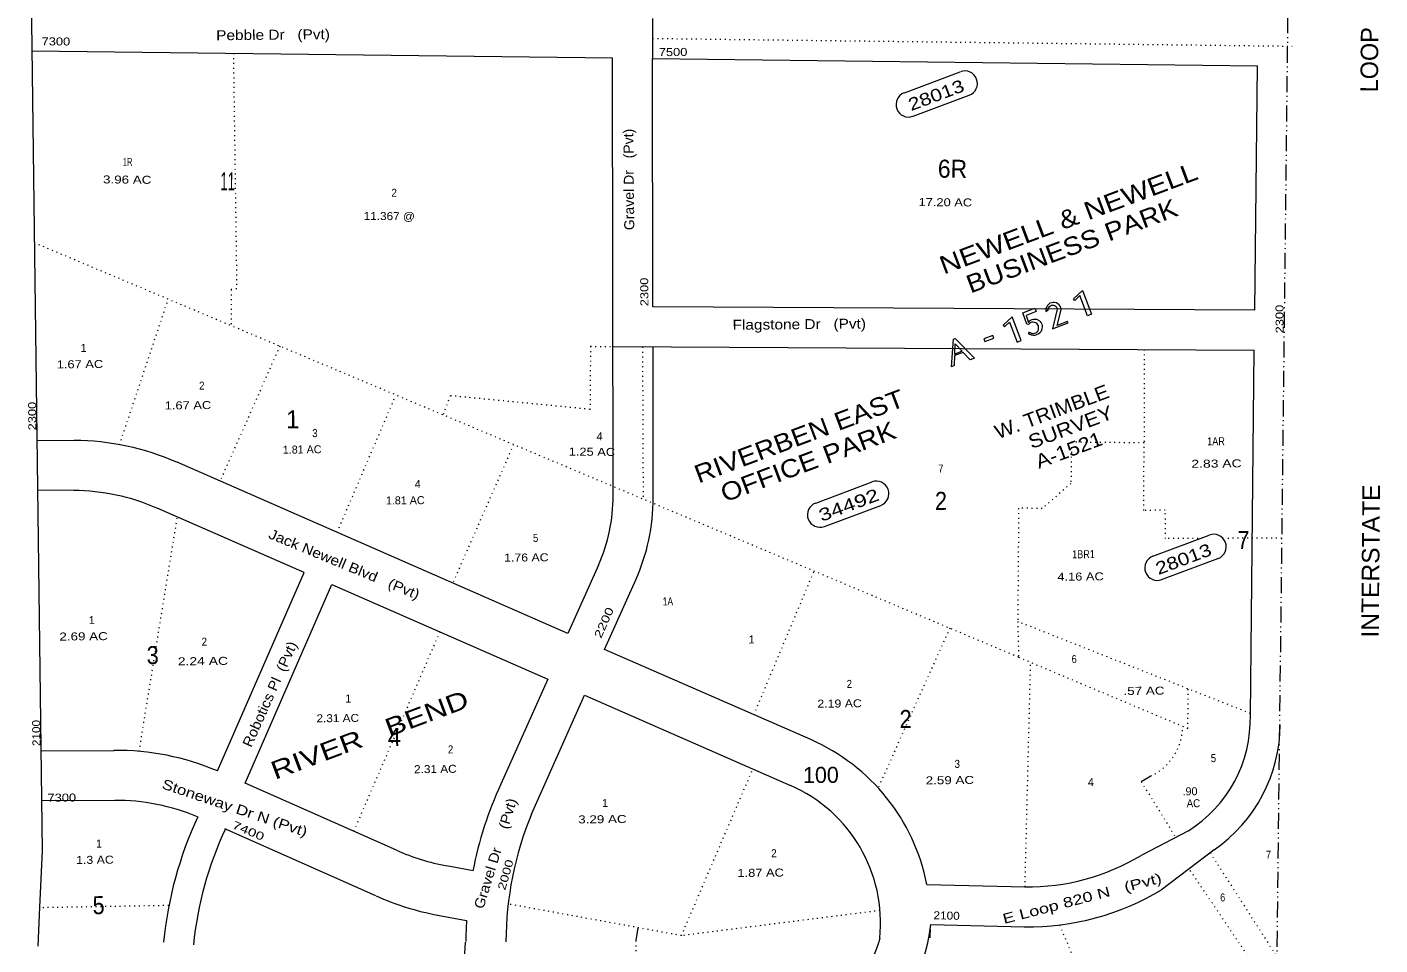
# Model space of a CAD drawing. Extents: x 2356373 to 2371954, y 6966197 to 6989612.
# Drawn here: x 2361765 to 2364467, y 6972847 to 6974681 of the extents above; entities that cross this region are included whole.
import ezdxf

# ---------------------------------------------------------------- set-up
doc = ezdxf.new("R2010")
doc.units = 0
doc.header["$LTSCALE"] = 6.4
doc.linetypes.add('DASH_DOUBLE_DOT', pattern=[9.2, 5, -1.2, 0.3, -1.2, 0.3, -1.2])
doc.linetypes.add('DOTTED', pattern=[1.5, 0.3, -1.2])
for name, color, linetype in [('11', 7, 'Continuous'), ('18', 7, 'Continuous'), ('20', 7, 'Continuous'), ('22', 7, 'Continuous'), ('24', 7, 'Continuous')]:
    doc.layers.add(name, color=color, linetype=linetype)
for name, color, linetype, lineweight in [('12', 7, 'Continuous', 13), ('15', 7, 'Continuous', 13), ('16', 7, 'DOTTED', 13), ('17', 7, 'Continuous', 13), ('19', 7, 'Continuous', 13), ('5', 7, 'DOTTED', 13), ('6', 7, 'DOTTED', 13)]:
    doc.layers.add(name, color=color, linetype=linetype, lineweight=lineweight)

msp = doc.modelspace()

# ---------------------------------------------------------------- linework, layer by layer
at = {"layer": '15', "linetype": 'DASH_DOUBLE_DOT'}
msp.add_line((2364294.614, 6975701.264), (2364247.909, 6971653.107), dxfattribs=at)
at = {"layer": '15'}
for p, q in [((2361774.551, 6974632.99), (2362934.731, 6974618.953)), ((2362935.771, 6973744.536), (2362934.731, 6974618.953)), ((2363014.689, 6974617.989), (2364222.53, 6974603.378)), ((2363015.284, 6974121.647), (2363014.689, 6974617.989)), ((2364217.257, 6974115.219), (2364222.53, 6974603.378)), ((2364217.257, 6974115.219), (2363015.284, 6974121.647)), ((2362935.416, 6974042.194), (2364216.393, 6974035.232)), ((2363015.745, 6973739.914), (2363015.39, 6974041.759)), ((2364208.53, 6973306.017), (2364216.393, 6974035.232)), ((2361784.87, 6973855.259), (2361859.855, 6973854.796)), ((2361858.837, 6973754.812), (2361785.852, 6973755.295)), ((2361792.967, 6973234.504), (2361938.916, 6973235.739)), ((2361939.898, 6973135.774), (2361793.949, 6973134.541)), ((2362461.636, 6972944.751), (2362160.4, 6973078.656)), ((2364084.743, 6973075.004), (2363990.121, 6973025.747)), ((2364136.511, 6973036.974), (2364031.245, 6972957.149)), ((2362656.089, 6972995.148), (2362603.008, 6973004.825)), ((2363562.334, 6972968), (2363758.901, 6972962.943)), ((2362584.978, 6972906.473), (2362643.067, 6972895.847)), ((2363570.22, 6972887.798), (2363756.836, 6972882.993))]:
    msp.add_line(p, q, dxfattribs=at)
for points in [[(2361751.375, 6976451.137), (2361794.929, 6973034.877), (2361790.036, 6972922.159), (2361786.8, 6972844.548)], [(2362906.235, 6973605.533), (2362845.379, 6973469.282), (2362065.228, 6973811.227)], [(2362145.264, 6973194.676), (2362318.326, 6973590.971), (2362025.139, 6973719.656)], [(2362502.726, 6973036.131), (2362200.488, 6973170.426), (2362373.546, 6973566.92), (2362805.287, 6973378.012), (2362711.393, 6973168.196)], [(2363330.334, 6973257.203), (2362918.675, 6973437.211), (2362980.844, 6973576.044)], [(2362772.585, 6973108.473), (2362878.583, 6973345.941), (2363290.246, 6973165.534)]]:
    msp.add_lwpolyline(points, dxfattribs=at)
for centre, radius, start, end in [((2361855.963, 6973334.997), 519.836, 66.35876, 89.63976), ((2361855.963, 6973334.997), 419.868, 66.35876, 89.63976), ((2362595.88, 6973744.122), 339.893, 335.93788, 0.07048), ((2362615.876, 6973739.444), 399.874, 335.88148, 0.0671), ((2363943.891, 6973299.153), 264.728, 302.14425, 1.4857), ((2363959.651, 6973289.944), 308.67, 304.95916, 359.53974), ((2363169.976, 6972890.825), 399.874, 11.12792, 66.35876), ((2361943.022, 6972715.917), 519.836, 67.07976, 90.47876), ((2363401.315, 6972850.009), 759.76, 155.24122, 168.98276), ((2363169.976, 6972890.825), 299.906, 354.18786, 66.36276), ((2361943.022, 6972715.917), 419.868, 67.19976, 90.47876), ((2362794.164, 6972780.162), 759.76, 154.86276, 174.52276), ((2363401.315, 6972850.009), 679.786, 157.65291, 179.73276), ((2362794.164, 6972780.162), 699.779, 154.75276, 174.52076), ((2362685.639, 6973447.218), 449.858, 246.03276, 259.51276), ((2363763.166, 6973404.304), 441.379, 269.36876, 300.94298), ((2362685.639, 6973447.218), 549.827, 246.03276, 259.51276), ((2363763.166, 6973404.304), 521.354, 269.36876, 300.94386), ((2363401.315, 6972850.009), 759.76, 176.54276, 179.73276), ((2363230.635, 6972923.912), 341.502, 304.42246, 353.92917), ((2363169.976, 6972890.825), 399.874, 355.78596, 358.23276), ((2363448.93, 6972786.194), 811.194, 175.32336, 187.81596), ((2363230.635, 6972923.912), 246.532, 303.19276, 345.08276)]:
    msp.add_arc(centre, radius, start, end, dxfattribs=at)
at = {"layer": '16'}
for p, q in [((2362994.387, 6974041.543), (2362995.593, 6973737.546)), ((2364208.566, 6973309.394), (2363743.906, 6973493.102))]:
    msp.add_line(p, q, dxfattribs=at)
msp.add_lwpolyline([(2363996.501, 6974036.44), (2363996.331, 6973849.989), (2363851.359, 6973851.164), (2363850.168, 6973768.874), (2363792.674, 6973718.923), (2363745.681, 6973719.461), (2363743.906, 6973493.102), (2363745.606, 6973421.739), (2361779.999, 6974249.406)], dxfattribs=at)
at = {"layer": '17'}
for p, q in [((2363517.589, 6974549.297), (2363629.146, 6974591.383)), ((2363535.044, 6974502.482), (2363646.602, 6974544.566)), ((2363340.688, 6973729.778), (2363453.243, 6973771.974)), ((2363358.142, 6973683.063), (2363470.698, 6973725.157)), ((2364013.551, 6973623.618), (2364126.107, 6973665.714)), ((2364031.006, 6973576.801), (2364143.562, 6973618.896))]:
    msp.add_line(p, q, dxfattribs=at)
for points in [[(2363873.394, 6974154.528), (2363891.353, 6974107.118), (2363883.386, 6974104.04), (2363867.996, 6974144.079), (2363858.098, 6974134.134), (2363855.064, 6974137.503), (2363873.394, 6974154.528)], [(2363824.166, 6974128.053), (2363821.152, 6974129.572), (2363817.645, 6974130.387), (2363814.645, 6974130.558), (2363811.15, 6974130.023), (2363808.162, 6974128.795), (2363805.682, 6974126.971), (2363803.205, 6974124.648), (2363801.732, 6974121.833), (2363800.264, 6974118.72), (2363800.296, 6974115.521), (2363800.328, 6974112.222), (2363804.79, 6974115.815), (2363805.268, 6974118.169), (2363805.746, 6974120.423), (2363807.227, 6974122.338), (2363809.21, 6974123.807), (2363811.2, 6974124.825), (2363813.697, 6974125.199), (2363816.198, 6974125.025), (2363818.705, 6974124.049), (2363820.723, 6974122.269), (2363822.245, 6974120.035), (2363822.771, 6974117.392), (2363822.297, 6974114.737), (2363813.162, 6974077.808), (2363844.538, 6974089.562), (2363843.514, 6974092.201), (2363822.595, 6974084.249), (2363830.311, 6974113.217), (2363830.776, 6974116.669), (2363830.244, 6974120.014), (2363828.713, 6974123.148), (2363826.685, 6974125.927), (2363824.166, 6974128.053)], [(2363732.947, 6974101.864), (2363714.62, 6974084.838), (2363717.652, 6974081.468), (2363727.553, 6974091.413), (2363742.942, 6974051.374), (2363750.908, 6974054.451), (2363732.947, 6974101.864)], [(2363753.866, 6974109.517), (2363778.269, 6974118.804), (2363780.834, 6974112.131), (2363760.415, 6974104.383), (2363765.549, 6974090.736), (2363767.024, 6974093.099), (2363769.507, 6974094.974), (2363772.492, 6974096.353), (2363775.483, 6974097.181), (2363778.479, 6974097.413), (2363781.483, 6974096.992), (2363783.992, 6974096.015), (2363786.507, 6974094.491), (2363789.025, 6974092.417), (2363790.549, 6974089.981), (2363792.075, 6974087.248), (2363792.605, 6974084.255), (2363792.635, 6974081.256), (2363792.164, 6974078.252), (2363791.196, 6974074.942), (2363789.726, 6974071.928), (2363787.252, 6974069.306), (2363784.775, 6974067.182), (2363781.291, 6974065.648), (2363778.3, 6974064.77), (2363774.801, 6974064.584), (2363771.299, 6974065.048), (2363768.288, 6974066.271), (2363765.27, 6974068.09), (2363767.242, 6974070.909), (2363769.756, 6974069.533), (2363772.263, 6974068.758), (2363774.764, 6974068.533), (2363777.259, 6974068.958), (2363779.749, 6974069.881), (2363782.234, 6974071.355), (2363783.714, 6974073.27), (2363785.193, 6974075.533), (2363785.666, 6974078.187), (2363785.639, 6974080.936), (2363785.113, 6974083.581), (2363784.09, 6974086.021), (2363782.568, 6974088.105), (2363780.055, 6974089.729), (2363777.546, 6974090.753), (2363775.042, 6974091.179), (2363772.045, 6974090.901), (2363769.554, 6974089.976), (2363767.069, 6974088.502), (2363765.589, 6974086.488), (2363762.088, 6974086.804), (2363753.866, 6974109.517)], [(2363618.907, 6974058.204), (2363657.278, 6974019.342), (2363648.812, 6974016.109), (2363635.172, 6974030.772), (2363617.74, 6974024.351), (2363616.937, 6974004.249), (2363611.46, 6974002.147), (2363615.421, 6974056.919), (2363618.907, 6974058.204)], [(2363619.007, 6974048.007), (2363632.651, 6974032.996), (2363618.209, 6974027.456), (2363619.007, 6974048.007)], [(2363695.876, 6974059.111), (2363693.825, 6974064.44), (2363676.393, 6974058.02), (2363678.445, 6974052.64), (2363695.876, 6974059.111)]]:
    msp.add_lwpolyline(points, close=True, dxfattribs=at)
for points in [[(2363804.79, 6974115.815), (2363800.328, 6974112.222), (2363804.79, 6974115.815)], [(2363767.242, 6974070.909), (2363765.27, 6974068.09), (2363767.242, 6974070.909)]]:
    msp.add_lwpolyline(points, dxfattribs=at)
for centre, start, end in [((2363638.373, 6974567.98), 290.56276, 110.56276), ((2363525.817, 6974525.885), 110.56276, 290.56276), ((2363461.471, 6973748.56), 290.56276, 110.56276), ((2363348.916, 6973706.366), 110.56276, 290.56276), ((2364135.335, 6973642.309), 290.56276, 110.56276), ((2364022.779, 6973600.215), 110.56276, 290.56276)]:
    msp.add_arc(centre, 24.992, start, end, dxfattribs=at)
at = {"layer": '5', "linetype": 'Continuous'}
msp.add_line((2363014.582, 6974697.975), (2363014.689, 6974617.989), dxfattribs=at)
at = {"layer": '6'}
for p, q in [((2363014.635, 6974657.988), (2364292.135, 6974642.524)), ((2361949.914, 6973846.282), (2362047.035, 6974136.76)), ((2362269.895, 6974043.074), (2362150.577, 6973773.474)), ((2362890.422, 6974042.951), (2362935.416, 6974042.194)), ((2362384.516, 6973671.4), (2362501.792, 6973945.479)), ((2362736.704, 6973846.315), (2362615.448, 6973570.296)), ((2361988.922, 6973233.73), (2362065.304, 6973701.655)), ((2364271.061, 6973659.786), (2364156.164, 6973659.209)), ((2363216.876, 6973306.875), (2363337.026, 6973593.679)), ((2362589.419, 6973472.266), (2362417.378, 6973073.883)), ((2363608.071, 6973479.872), (2363465.242, 6973161.155)), ((2363758.43, 6972962.949), (2363769.7, 6973411.578)), ((2363072.251, 6972865.571), (2363214.938, 6973198.784)), ((2363990.644, 6973173.123), (2364059.722, 6973061.432)), ((2364128.26, 6973031.393), (2364261.416, 6972823.486)), ((2364256.048, 6972747.083), (2364086.3, 6972998.9)), ((2362047.934, 6972925.692), (2361790.046, 6972921.26))]:
    msp.add_line(p, q, dxfattribs=at)
at = {"layer": '6', "linetype": 'Continuous'}
for p, q in [((2364009.527, 6973184.406), (2363990.644, 6973173.123)), ((2362985.118, 6972881.312), (2362981.372, 6972855.682))]:
    msp.add_line(p, q, dxfattribs=at)
at = {"layer": '6'}
for points in [[(2362177.172, 6974628.117), (2362183.792, 6974157.699), (2362172.81, 6974156.191), (2362172.52, 6974084.008)], [(2362890.422, 6974042.951), (2362889.659, 6973916.877), (2362610.467, 6973944.127), (2362595.685, 6973905.941)], [(2364104.18, 6973659), (2364039.201, 6973658.661), (2364038.642, 6973715.44), (2363995.658, 6973715.018), (2363996.331, 6973849.989)], [(2363745.606, 6973421.739), (2364083.915, 6973279.401), (2364084.137, 6973358.481)], [(2363468.652, 6972915.653), (2363072.251, 6972865.571), (2362726.723, 6972928.66)], [(2363827.429, 6972886.927), (2363966.031, 6972558.235), (2363556.855, 6972281.989)], [(2362981.372, 6972855.682), (2362979.014, 6972688.604), (2362737.57, 6972638.544)]]:
    msp.add_lwpolyline(points, dxfattribs=at)
msp.add_arc((2363963.197, 6973284.424), 110.225, 294.85276, 359.68416, dxfattribs=at)

# ---------------------------------------------------------------- texts
at = {"layer": '11'}
for s, rotation, width, p in [('3.96 AC', 359.503, 1.25, (2361916.794, 6974368.318)), ('17.20 AC', 359.503, 1.2, (2363545.804, 6974323.136)), ('11.367 @', 359.503, 1.1, (2362437.371, 6974295.452)), ('1.67 AC', 0.563, 1.2, (2361824.451, 6973998.709)), ('1.67 AC', 0.563, 1.2, (2362040.2, 6973916.651)), ('1.25 AC', 359.503, 1.2, (2362846.887, 6973824.602)), ('2.83 AC', 0.563, 1.3, (2364090.797, 6973800.129)), ('1.76 AC', 0.563, 1.15, (2362718.005, 6973612.593)), ('4.16 AC', 0.563, 1.2, (2363823.086, 6973574.459)), ('2.69 AC', 0.563, 1.25, (2361829.791, 6973455.008)), ('2.24 AC', 0.563, 1.3, (2362066.214, 6973405.543)), ('2.19 AC', 0.563, 1.15, (2363343.705, 6973320.917)), ('.57 AC', 0.563, 1.25, (2363955.291, 6973346.319)), ('2.31 AC', 0.563, 1.1, (2362343.257, 6973291.695)), ('2.31 AC', 0.563, 1.1, (2362538.204, 6973190.038)), ('2.59 AC', 0.563, 1.25, (2363560.153, 6973167.684)), ('AC', 0.563, 0.9, (2364081.462, 6973121.92)), ('3.29 AC', 0.563, 1.25, (2362866.104, 6973089.686)), ('1.3 AC', 0.563, 1.15, (2361863.167, 6973008.655)), ('1.87 AC', 0.563, 1.2, (2363184.069, 6972982.739))]:
    msp.add_text(s, height=15.99, rotation=rotation, dxfattribs=dict(at, width=width)).set_placement(p)
for s, p in [('1.81 AC', (2362276.003, 6973828.392)), ('1.81 AC', (2362481.946, 6973726.842)), ('.90', (2364073.229, 6973145.832))]:
    msp.add_text(s, height=15.99, rotation=0.563, dxfattribs=at).set_placement(p)
at = {"layer": '12'}
for s, rotation, width, p in [('1R', 359.503, 0.7, (2361956.438, 6974403.499)), ('2', 359.503, 0.9, (2362492.902, 6974341.686)), ('2', 0.563, 0.9, (2362108.792, 6973956.215)), ('3', 0.563, 0.9, (2362334.663, 6973861.359)), ('1AR', 0.563, 0.85, (2364122.347, 6973845.028)), ('7', 0.563, 0.9, (2363585.026, 6973790.562)), ('5', 0.563, 0.9, (2362775.603, 6973652.047)), ('1BR1', 0.563, 0.85, (2363852.636, 6973619.337)), ('1A', 0.563, 0.8, (2363034.781, 6973525.127)), ('2', 0.563, 0.9, (2362113.815, 6973444.801)), ('6', 0.563, 0.85, (2363851.693, 6973410.085)), ('2', 0.563, 0.9, (2363402.301, 6973360.383)), ('2', 0.563, 0.9, (2362605.799, 6973229.593)), ('3', 0.563, 0.9, (2363617.812, 6973200.642)), ('5', 0.563, 0.9, (2364129.563, 6973212.168)), ('2', 0.563, 0.9, (2363251.663, 6973022.194)), ('7', 0.563, 0.9, (2364239.432, 6973018.999)), ('6', 0.563, 0.85, (2364148.292, 6972933.926))]:
    msp.add_text(s, height=15.99, rotation=rotation, dxfattribs=dict(at, width=width)).set_placement(p)
for s, rotation, p in [('1', 0.563, (2361872.115, 6974031.569)), ('4', 359.503, (2362902.575, 6973854.941)), ('4', 0.563, (2362539.607, 6973759.8)), ('1', 0.563, (2361888.453, 6973487.875)), ('1', 0.563, (2363206.481, 6973449.134)), ('1', 0.563, (2362400.854, 6973331.151)), ('4', 0.563, (2363884.097, 6973164.368)), ('1', 0.563, (2362913.769, 6973122.446)), ('1', 0.563, (2361902.835, 6973041.336))]:
    msp.add_text(s, height=15.99, rotation=rotation, dxfattribs=at).set_placement(p)
at = {"layer": '17'}
for s, width, p in [('28013', 1.25, (2363530.946, 6974512.639)), ('34492', 1.35, (2363352.056, 6973692.101)), ('28013', 1.25, (2364024.92, 6973585.841))]:
    msp.add_text(s, height=24.99, rotation=20.563, dxfattribs=dict(at, width=width)).set_placement(p)
at = {"layer": '18'}
for s, rotation, width, p in [('NEWELL & NEWELL', 20.563, 1.2, (2363596.137, 6974186.067)), ('BUSINESS PARK', 20.563, 1.15, (2363649.495, 6974148.201)), ('RIVERBEN EAST', 20.563, 1.15, (2363106.367, 6973768.666)), ('OFFICE PARK', 20.563, 1.15, (2363158.727, 6973730.79)), ('3', 0.563, 0.9, (2362004.208, 6973407.833)), ('RIVER   BEND', 20.563, 1.3, (2362260.411, 6973176.713)), ('2', 0.563, 0.9, (2363508.06, 6973280.242)), ('5', 0.563, 0.9, (2361896.144, 6972908.305))]:
    msp.add_text(s, height=35.99, rotation=rotation, dxfattribs=dict(at, width=width)).set_placement(p)
for s, height, p in [('4', 35.99, (2362485.686, 6973244.307)), ('100', 31.99, (2363315.191, 6973170.277))]:
    msp.add_text(s, height=height, rotation=0.563, dxfattribs=at).set_placement(p)
at = {"layer": '19'}
for s, height, rotation, width, p in [('Pebble Dr   (Pvt)', 19.99, 0.563, 1.15, (2362142.924, 6974654.263)), ('Gravel Dr   (Pvt)', 19.99, 90.563, 1.05, (2362978.008, 6974274.93)), ('Flagstone Dr   (Pvt)', 19.99, 0.563, 1.15, (2363174.363, 6974075.781)), ('INTERSTATE', 34.99, 89.556, 1.05, (2364465.03, 6973460.896)), ('Jack Newell Blvd   (Pvt)', 19.99, 337.509, 1.15, (2362245.663, 6973660.239)), ('Robotics Pl  (Pvt)', 19.99, 65.993, 1.1, (2362212.798, 6973240.228)), ('Stoneway Dr N (Pvt)', 19.98, 341.338, 1.25, (2362032.634, 6973160.18)), ('Gravel Dr     (Pvt)', 19.99, 72.921, 1.1, (2362676.416, 6972917.549)), ('E Loop 820 N   (Pvt)', 19.99, 14.697, 1.35, (2363716.85, 6972888.799))]:
    msp.add_text(s, height=height, rotation=rotation, dxfattribs=dict(at, width=width)).set_placement(p)
msp.add_text('LOOP', height=34.99, rotation=89.556, dxfattribs=at).set_placement((2364463.328, 6974550.189))
at = {"layer": '20'}
for s, width, p in [('W. TRIMBLE', 1.1, (2363704.341, 6973857.018)), ('SURVEY', 1.15, (2363771.516, 6973837.383)), ('A-1521', 1.15, (2363785.898, 6973798.034))]:
    msp.add_text(s, height=27.99, rotation=20.563, dxfattribs=dict(at, width=width)).set_placement(p)
at = {"layer": '22'}
for s, rotation, width, p in [('11', 359.503, 0.55, (2362150.866, 6974354.623)), ('6R', 359.503, 0.95, (2363584.237, 6974379.798)), ('2', 0.563, 0.9, (2363578.76, 6973716.02)), ('7', 359.503, 0.9, (2364182.365, 6973638.073))]:
    msp.add_text(s, height=35.99, rotation=rotation, dxfattribs=dict(at, width=width)).set_placement(p)
msp.add_text('1', height=35.99, rotation=0.563, dxfattribs=at).set_placement((2362282.503, 6973879.042))
at = {"layer": '24'}
for s, rotation, width, p in [('7300', 359.78, 1.2, (2361794.118, 6974644.039)), ('7500', 0.563, 1.2, (2363027.001, 6974622.457)), ('2300', 90.563, 1.2, (2363006.273, 6974123.018)), ('2300', 90.563, 1.2, (2364275.107, 6974068.868)), ('2300', 90.563, 1.2, (2361783.675, 6973875.042)), ('2200', 66.174, 1.35, (2362911.64, 6973458.236)), ('2100', 90.992, 1.1, (2361791.871, 6973244.291)), ('7300', 0.563, 1.2, (2361805.962, 6973132.959)), ('7400', 337.059, 1.4, (2362173.377, 6973080.683)), ('2000', 74.175, 1.3, (2362720.112, 6972955.339)), ('2100', 358.59, 1.1, (2363575.514, 6972898.368))]:
    msp.add_text(s, height=15.99, rotation=rotation, dxfattribs=dict(at, width=width)).set_placement(p)

doc.saveas('drawing.dxf')
